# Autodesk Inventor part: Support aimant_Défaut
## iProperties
Shininess: 64.0
Length Units: 11269
Angle Units: 11279
Time Units: 11290
Mass Units: 11283
Length Display Precision: 3
Angle Display Precision: 2
Compacted: True
Part Number: Support aimant_Défaut
Document SubType Name: Modeling
Created: 2006-01
Material: Par défaut
Designer: Fricot
Density: 0.0
Volumn: 0.0
Area: 0.0
PropertySet Name: Model Information
Control State: 0
Master: False
Checked Out: False
Author: Fricot
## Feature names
1. Base1
